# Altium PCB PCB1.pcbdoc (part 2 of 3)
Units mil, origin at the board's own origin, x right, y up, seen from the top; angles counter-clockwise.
Board outline 4706 x 2788 mil, 2 copper layers (Top Layer, Bottom Layer); 153 components, 206 nets, 1095 pads, 513 vias.
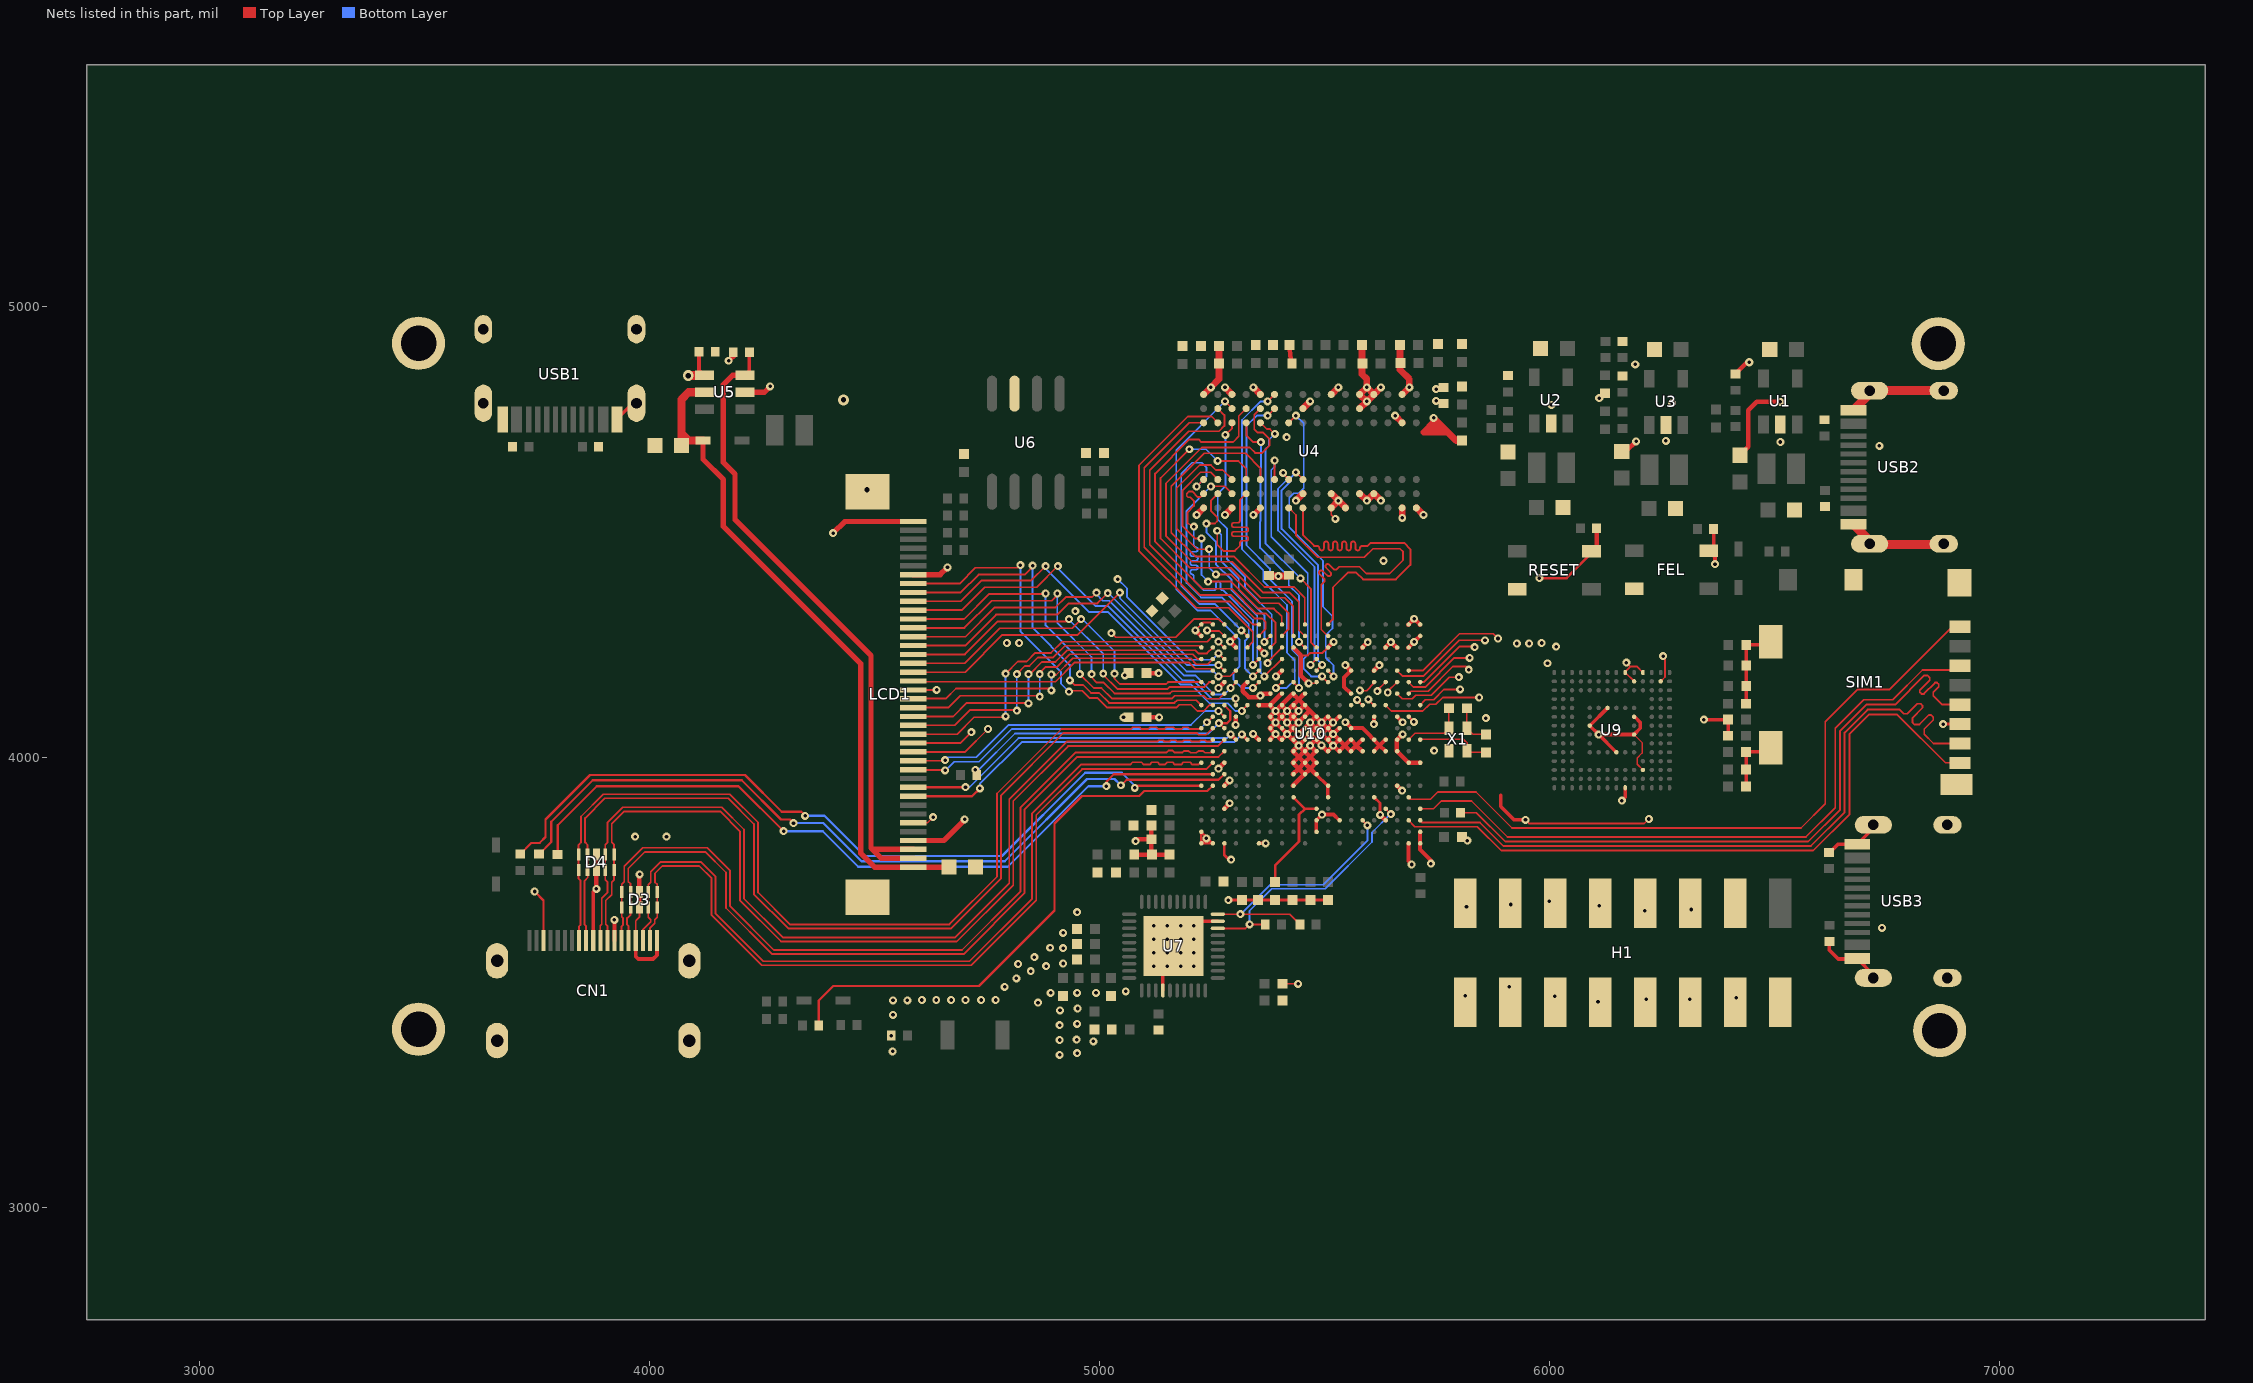
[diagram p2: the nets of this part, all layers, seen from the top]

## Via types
v1: diameter 17.7, hole 7.9, Top Layer to Bottom Layer, 233 vias
v2: diameter 17.72, hole 7.87, Top Layer to Bottom Layer, 140 vias
v3: diameter 17.7, hole 8, Top Layer to Bottom Layer, 88 vias
v4: diameter 18, hole 8, Top Layer to Bottom Layer, 38 vias
v5: diameter 24, hole 15, Top Layer to Bottom Layer, 8 vias
v6: diameter 24, hole 12, Top Layer to Bottom Layer, 6 vias

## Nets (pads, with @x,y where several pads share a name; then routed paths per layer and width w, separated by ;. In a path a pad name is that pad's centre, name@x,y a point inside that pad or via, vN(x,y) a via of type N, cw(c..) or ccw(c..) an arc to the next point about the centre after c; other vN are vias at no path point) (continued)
FEL: FEL.2 R36.2 U10.A18 | length 2083.2
  Top Layer w6: U10.A18@5276.7,3808.37 5276.7,3782.8 5277.5,3782 ; v1(5292,3772.5) v1@5287,3772.5 ; 5277.5,3782 5286,3772.5 v1@5287,3772.5 ; 5277.5,3782 v1@5287,3772.5
  Top Layer w8: R36.2@6364,4506.5 6364,4470.1 FEL.2@6352.7,4458.8 6367,4444.5 v1(6367,4428.5)
  Mid-Layer 1 w6: v1(5292,3772.5) 5301,3781.5 5633,3781.5 5678,3736.5 5869,3736.5 5909,3776.5 5909,3920.5 5963,3974.5 5963,4047.5 5902,4108.5 5805,4108.5 5768,4145.5 5768,4204.5 5917,4353.5 6292,4353.5 v1(6367,4428.5)
GND: C1.1 C2.1 C3.1 C5.1 C6.1 C7.1 C8.1 C9.1 C11.1 C12.1 C13.1 C15.1 C16.1 C17.1 C18.1 C19.1 C20.1 C21.1 C22.1 C23.1 C24.1 C25.1 C26.1 C27.1 C28.1 C29.1 C30.1 C31.1 C32.2 C33.1 C34.1 C35.1 C36.2 C38.1 C39.1 C40.1 C41.1 C42.1 C43.1 C44.1 C45.1 C46.1 C47.1 C48.1 C49.1 C50.1 C51.1 C52.1 C53.1 C54.1 C55.2 C56.1 C57.1 C58.1 C59.2 C60.2 C61.2 C62.2 C63.2 C64.2 C65.2 C66.2 C67.2 C68.1 C69.2 C70.1 C71.2 C72.1 C73.2 C74.1 CN1.1 CN1.4 CN1.7 CN1.10 CN1.17 CN1.20 CN1.21 CN1.22 CN1.23 D3.3 D3.8 D4.3 D4.8 FEL.3 H1.14 H1.15 LCD1.4 LCD1.34 LCD1.40 LCD1.41 LCD1.42 pad.1 R2.1 R4.1 R6.1 R8.1 R9.2 R10.2 R12.1 R14.1 R15.1 R16.1 R17.1 R18.2 R19.2 R20.2 R21.1 R22.1 R29.1 R32.2 R33.2 RESET.3 SIM1.6 SIM1.9 SIM1.10 SIM1.11 SIM1.13 SIM1.14 U1.2 U2.2 U3.2 U4.A9 U4.B1 U4.B3 U4.B9 U4.D1 U4.D8 U4.E1 U4.E2 U4.E8 U4.F9 U4.G1 U4.G8 U4.G9 U4.J2 U4.J8 U4.M1 U4.M9 U4.P1 U4.P9 U4.T1 U4.T9 U5.2 U6.3 U7.4 U7.19 U7.41 U9.A6 U9.C4 U9.E7 U9.G5 U9.H10 U9.J5 U9.K8 U9.N2 U9.N5 U9.P4 U9.P6 U10.A1 U10.A2 U10.A15 U10.A19 U10.A20 U10.B1 U10.B10 U10.B20 U10.C4 U10.C8 U10.C10 U10.D18 U10.E5 U10.E9 U10.F3 U10.F9 U10.F12 U10.F18 U10.G10 U10.G11 U10.G12 U10.H1 U10.H2 U10.H10 U10.H11 U10.H12 U10.H18 U10.J3 U10.J6 U10.J7 U10.J8 U10.J9 U10.J10 U10.J11 U10.J12 U10.K3 U10.K6 U10.K7 U10.K8 U10.K9 U10.K10 U10.K11 U10.K12 U10.K13 U10.K14 U10.L8 U10.L9 U10.L10 U10.L11 U10.L12 U10.L13 U10.L14 U10.L18 U10.M3 U10.M5 U10.M8 U10.M9 U10.M10 U10.M11 U10.M12 U10.M13 U10.M14 U10.N11 U10.N12 U10.N13 U10.N14 U10.N15 U10.N18 U10.P7 U10.P11 U10.P12 U10.P13 U10.R10 U10.R18 U10.T5 U10.T7 U10.T13 U10.V2 U10.V3 U10.V4 U10.V6 U10.V9 U10.V12 U10.V15 U10.V17 U10.W1 U10.W17 U10.W20 U10.Y1 U10.Y2 U10.Y19 U10.Y20 USB1.13 USB1.14 USB1.15 USB1.16 USB1.A1B12 USB1.B1A12 USB2.13 USB2.14 USB2.15 USB2.16 USB2.A1B12 USB2.B1A12 USB3.13 USB3.14 USB3.15 USB3.16 USB3.A1B12 USB3.B1A12 X1.2 X1.4 | length 9502.7
  Top Layer w3.5: C36.2@5816,4108.5 X1.2@5816,4064.5 5830,4050.5 C32.2@5858,4050.51 ; U9.G5@6187.24,4050.18 6205.02,4032.39 6205.02,4009.03 6194.02,3998.03 6194.02,3984.34 U9.C4@6206.92,3971.44 ; U9.N2@6246.29,4168.29 6256,4178 6256,4214.5 6256,4220.5 v1(6252,4224.5)
  Top Layer w4: CN1.4@3969.5,3592.7 3969.5,3636 3971,3637.5 3977.7,3644.2 D3.8@3977.7,3665.5 ; v2(5212.54,4281.78) 5212.71,4281.78 5229.93,4299 5246.7,4299 U10.Y19@5251.11,4294.59 ; v3(5265,4075.5) 5265,4075.99 5265.48,4075.5 U10.L18@5276.7,4064.28 ; U10.R18@5276.7,4166.2 U10.R18@5276.7,4166.64 ; C60.2@5406,3496.5 v1(5441,3496.5) ; v2(5464.24,4163.89) 5478.68,4163.89 U10.R10@5481.43,4166.64 ; U4.G9@5514.5,4553.65 5514.5,4538.15 v2(5523.5,4529.15) ; v2(5530.49,4569.65) U4.F9@5546,4553.65 ; v1(5946,3860.5) 5954,3852.5 5982.5,3852.5 6210,3852.5 v1(6220,3862.5) ; v1(6170.02,4210.02) 6179.02,4201.02 ; U9.N5@6187.24,4168.29 U9.P6@6167.55,4187.98 6167.55,4189.55 6179.02,4201.02 ; U9.P4@6206.92,4187.98 6193.87,4201.02 6179.02,4201.02
  Top Layer w4.5: 5447.24,4226.2 5462.54,4226.2 5467.58,4231.24 5494.68,4231.24 U10.V9@5506.83,4243.39
  Top Layer w5: v1(3745,3701.5) 3764.8,3681.7 CN1.17@3764.8,3591.7 ; v3(5265,4075.5) 5265.48,4075.5 5283,4075.5 5290,4082.5 5290,4102.17 U10.N18@5276.7,4115.46 ; v1(5288.88,3948.5) v1@5289,3948.5
  Top Layer w6: v1(5286,3682.51) C2.1@5316,3682.51 C3.1@5352,3682.51 C9.1@5390,3682.51 C23.1@5428,3682.51 C19.1@5468,3682.51 C21.1@5507,3682.51 ; U10.E5@5609.88,3910.88 5623,3897.76 v1(5623,3871.5) ; v1(6874,4073.5) SIM1.6@6911.1,4073.5 ; U10.A20@5225.87,3808.37 v1(5237,3819.5) ; U10.A20@5225.87,3808.37 5225.52,3808.37 5225.52,3833.96 5237,3822.49 v1(5237,3819.5) ; U10.A20@5225.87,3808.37 5251.11,3808.37 5239.98,3819.5 v1(5237,3819.5)
  Top Layer w8: CN1.10@3875,3592.7 3875,3700.5 v3(3882,3707.5) ; CN1.7@3922.2,3592.7 v1@3922.2,3638.5 ; USB1.A1B12@3928.28,4751.52 3964.3,4787.54 USB1.13@3971.38,4787.54 ; CN1.4@3969.5,3592.7 3969.5,3557 3975,3551.5 4008,3551.5 4016.7,3560.2 CN1.1@4016.7,3592.7 ; U7.4@5140.54,3481.8 5140.54,3526.04 v4(5150,3535.5) ; v4(5209,3625.5) 5218.81,3635.32 U7.19@5262.56,3635.32 ; U10.A15@5353.47,3808.37 v1(5368.87,3808.37) v1@5369,3808.5 ; U10.G10@5480.43,3961.71 5507.02,3936.32 U10.E9@5507.02,3910.73 ; U10.B10@5481.43,3833.96 5481.43,3859.55 v1(5494,3872.12) 5494,3872.5 5519.66,3872.5 U10.C8@5532.61,3859.55 ; U10.M5@5609.38,4089.87 v1@5609.38,4075.88 ; U10.M3@5660.63,4089.87 v1(5673,4077.5) ; U10.A2@5686.15,3808.37 5686.15,3768.35 v1(5693,3761.5) ; U10.B1@5711.74,3833.96 5711.74,3794.76 5736,3770.5 v1(5736,3763.5) ; 5891,3915.5 5891,3890.5 5921,3860.5 v1(5946,3860.5) ; U9.K8@6128.18,4109.24 U9.H10@6088.81,4069.87 v1(6108.5,4050.18) ; U9.E7@6147.87,4010.81 v1(6108.5,4050.18) ; v1(6160,3903.5) 6167.55,3911.05 U9.A6@6167.55,3932.07 ; U9.J5@6187.24,4089.55 6188.5,4089.55 6201.02,4077.03 6201.02,4063.97 U9.G5@6187.24,4050.18 v1(6108.5,4050.18) ; v1@6342,4083.5 v1(6342.3,4083.2) C28.1@6395.95,4083.2 ; C29.1@6396,4047.5 C28.1@6395.95,4083.2 ; C68.1@6435.99,3934.5 C70.1@6435.99,3972.5 C72.1@6435.99,4011.5 6481.5,4011.5 SIM1.14@6490.9,4020.9 ; C25.1@6435.99,4118.5 6436.36,4118.87 C73.2@6436.36,4157.85 C71.2@6436.36,4203.53 C69.2@6436.36,4249.22 6484.12,4249.22 SIM1.13@6490.9,4256 ; R20.2@6620,3788.5 6622.4,3788.5 6640.17,3806.27 USB3.B1A12@6682.71,3806.27 6718.73,3842.29 USB3.14@6718.73,3849.58 ; R17.1@6621,3590.5 6621,3571.5 6641,3551.5 6681.68,3551.5 USB3.A1B12@6682.71,3552.53 6718.73,3516.51 USB3.13@6718.73,3509.43 ; v1@5609.38,4075.88 5609,4075.5 5609.38,4073.5 v1@5609.38,4075.88
  Top Layer w9: U10.T7@5558.01,4192.21 5543,4177.2 5543,4156.26 U10.P7@5558.2,4141.05 ; U10.K7@5558.2,4038.68 5570.6,4026.29 5583.39,4013.49 U10.J6@5583.79,4013.09
  Top Layer w10: v3(3882,3707.5) D4.8@3882,3749.2 D4.3@3882,3783.8 ; D3.8@3977.7,3665.5 D3.3@3977.7,3700.1 3977.7,3739.2 v3(3978,3739.5) ; C59.2@5077,3783.51 C66.2@5116,3783.51 ; v1(5080,3813.5) 5084,3817.5 C30.1@5115,3817.5 ; C1.1@5115,3848.5 C30.1@5115,3817.5 ; C64.2@5155,3783.51 C66.2@5116,3783.51 ; v2(5212.54,4281.78) U10.W20@5225.33,4268.98 ; v1(5264,3974.5) 5277,3987.5 U10.H18@5276.7,3987.5 ; v1(5264,4153.5) 5264,4153.94 U10.R18@5276.7,4166.64 ; U10.D18@5276.7,3885.14 v1@5289,3897.44 ; U10.F18@5276.7,3936.32 v1(5288.88,3948.5) ; U10.V17@5302.1,4243.39 5302.1,4244.39 v2(5290,4256.5) 5302.1,4268.61 U10.W17@5302.1,4268.98 ; U10.N15@5352.47,4115.26 U10.N14@5378.06,4115.26 ; U10.V15@5353.28,4243.39 v2(5366.08,4230.6) ; U10.K14@5378.06,4038.48 v1(5390.86,4051.28) ; v2(5391.67,4179.42) U10.T13@5404.46,4192.21 ; U10.P13@5402.21,4139.42 U10.N14@5378.06,4115.26 ; C39.1@5421.71,4915.46 ccw(c5571.82,4915.46) R14.1@5427.5,4874.16 ; U10.F12@5429.24,3936.12 U10.G11@5454.83,3961.71 ; U10.G12@5429.24,3961.71 5442.04,3974.51 ; U10.V12@5430.05,4243.39 5447.24,4226.2 5447.24,4180.89 v2(5464.24,4163.89) ; v1(5442.04,4102.47) U10.M12@5429.24,4089.67 ; U10.P11@5453.39,4139.42 5442.04,4128.06 ; 5467.02,4101.86 5467.02,4103.08 ; U10.J10@5480.42,4012.89 5467.63,4000.1 ; U10.G10@5480.43,3961.71 5467.63,3974.51 ; U10.J10@5480.43,4012.89 v1(5467.63,4025.69) ; U10.V9@5506.83,4243.39 v2(5519.63,4256.19) ; U10.L8@5531.61,4064.07 v1(5518.82,4051.28) ; U10.M8@5531.61,4089.67 v1(5518.82,4076.88) ; v2(5546.01,4204.21) U10.T7@5558.01,4192.21 ; U10.K7@5557.2,4038.48 5544.41,4025.69 ; U10.K6@5582.79,4038.48 5570.6,4026.29 5570,4025.69 ; U10.J6@5583.39,4013.49 5570,4025.69 ; U10.V6@5583.6,4243.39 v2(5595.6,4255.39) ; U10.T5@5609.19,4192.21 v2(5621.19,4204.21) ; v1(5623,3871.5) 5623.67,3871.5 U10.C4@5635.47,3859.7 ; U10.V4@5634.78,4243.39 v2(5646.78,4255.39) U10.V3@5660.37,4243.39 ; U10.F3@5660.56,3936.32 5671.39,3925.5 v1(5672,3925.5) ; v1(5673,4050.5) 5672.38,4050.5 5660.56,4038.68 5660.56,4013.09 5686.15,3987.5 U10.H1@5711.74,3987.5 ; U10.V2@5685.96,4243.39 v2(5698.76,4256.19) U10.W1@5711.55,4268.98 ; U10.Y2@5685.96,4294.57 v2(5698.76,4307.37) U10.Y1@5711.55,4294.57 ; C16.1@6159.87,4678.92 6169.4,4678.92 v4(6191.87,4701.4) ; R2.1@6412.14,4851.11 6438.15,4877.11 v4(6443.14,4877.11) ; C6.1@6422.14,4670.64 6441,4689.49 6441,4739.5 6441,4770.5 6460,4789.5 6511.75,4789.5 v4(6512.14,4789.11) ; USB2.A1B12@6674.55,4509.87 USB2.A1B12@6674.55,4516.95 ; C30.1@5115,3817.5 5115,3784.5 C66.2@5116,3783.51 ; U10.N14@5378.06,4115.26 v1(5390.86,4102.47) ; v1(5390.86,4051.28) 5378.06,4064.08 v1(5390.86,4076.88) ; v1(5390.86,4051.28) 5403.65,4038.49 v1(5416.45,4051.28) ; v1(5390.86,4076.88) U10.M13@5403.65,4089.67 ; v1(5390.86,4076.88) 5378.06,4089.67 v1(5390.86,4102.47) ; v1(5390.86,4076.88) v1(5416.45,4051.28) ; v1(5390.86,4102.47) U10.N13@5403.65,4115.26 ; v1(5390.86,4102.47) U10.M13@5403.65,4089.67 ; U10.M13@5403.65,4089.67 v1(5416.45,4102.47) ; U10.M13@5403.65,4089.67 v1@5416.45,4076.87 ; U10.N13@5403.65,4115.26 v1(5416.45,4102.47) ; U10.N13@5403.65,4115.26 5429.24,4140.85 5442.04,4128.06 ; v1(5416.45,4051.28) U10.L12@5429.25,4064.08 ; v1(5416.45,4051.28) U10.K12@5429.25,4038.49 ; v1@5416.47,4076.86 U10.M12@5429.24,4089.67 ; v1@5416.47,4076.86 U10.L12@5429.25,4064.08 ; v1(5416.45,4102.47) U10.M12@5429.24,4089.67 ; v1(5416.45,4102.47) U10.N12@5429.24,4115.26 ; U10.K12@5429.25,4038.49 v1(5442.04,4051.28) ; U10.K12@5429.25,4038.49 v1(5442.04,4025.69) ; U10.L12@5429.25,4064.08 v1(5442.04,4051.28) ; U10.L12@5429.25,4064.08 v1(5442.04,4076.87) ; U10.M12@5429.24,4089.67 v1(5442.04,4076.87) ; U10.N12@5429.24,4115.26 5442.04,4128.06 ; U10.N12@5429.24,4115.26 v1(5442.04,4102.47) U10.N11@5454.84,4115.27 ; 5442.04,3974.51 5429.24,3987.3 5442.04,4000.1 ; 5442.04,3974.51 U10.G11@5454.83,3961.71 ; 5442.04,3974.51 U10.H11@5454.84,3987.31 ; 5442.04,4000.1 5429.25,4012.89 v1(5442.04,4025.69) ; 5442.04,4000.1 U10.H11@5454.84,3987.31 ; 5442.04,4000.1 U10.J11@5454.83,4012.89 ; v1(5442.04,4025.69) U10.J11@5454.83,4012.89 ; v1(5442.04,4025.69) U10.J11@5454.84,4012.9 ; v1(5442.04,4025.69) v1(5467.63,4051.28) ; v1(5442.04,4051.28) v1(5467.63,4076.87) ; v1(5442.04,4076.87) 5442.04,4078.1 5467.02,4103.08 ; 5442.04,4128.06 U10.N11@5454.84,4115.27 ; U10.G11@5454.83,3961.71 5467.63,3974.51 ; U10.H11@5454.84,3987.31 5467.63,3974.51 ; U10.H11@5454.84,3987.31 5467.63,4000.1 ; U10.J11@5454.84,4012.9 v1(5467.63,4025.69) ; U10.J11@5454.84,4012.9 5467.63,4000.1 ; U10.N11@5454.84,4115.27 5467.02,4103.08 ; 5467.02,4103.08 U10.M10@5480.43,4089.67 ; 5467.63,3974.51 5480.42,3987.3 5467.63,4000.1 ; v1(5467.63,4025.69) U10.K10@5480.43,4038.49 ; v1(5467.63,4051.28) U10.K10@5480.43,4038.49 ; v1(5467.63,4051.28) U10.L10@5480.43,4064.08 ; v1(5467.63,4076.87) U10.L10@5480.43,4064.08 ; v1(5467.63,4076.87) U10.M10@5480.43,4089.67 ; U10.K10@5480.43,4038.49 v1(5493.22,4051.28) ; U10.K10@5480.43,4038.49 v1(5492.91,4026.01) 5506.02,4012.89 v1(5518.82,4025.69) ; U10.L10@5480.43,4064.08 v1(5493.22,4051.28) ; U10.L10@5480.43,4064.08 v1(5493.23,4076.88) ; U10.M10@5480.43,4089.67 v1(5493.23,4076.88) ; v1(5493.22,4051.28) U10.L9@5506.02,4064.08 ; v1(5493.22,4051.28) U10.K9@5506.02,4038.48 ; v1(5493.23,4076.88) 5506.02,4089.67 v1(5518.82,4076.88) ; v1(5493.23,4076.88) U10.L9@5506.02,4064.08 ; U10.K9@5506.02,4038.48 v1(5518.82,4025.69) ; U10.K9@5506.02,4038.48 v1(5518.82,4051.28) ; U10.L9@5506.02,4064.08 v1(5518.82,4076.88) ; U10.L9@5506.02,4064.08 v1(5518.82,4051.28) ; v1(5518.82,4025.69) U10.K8@5531.62,4038.49 ; v1(5518.82,4025.69) 5531.61,4012.89 5544.41,4025.69 ; v1(5518.82,4051.28) U10.K8@5531.62,4038.49 ; U10.K8@5531.62,4038.49 5544.41,4025.69 ; 5544.41,4025.69 5557.2,4012.9 5570,4025.69
  Top Layer w12: v1(4176,4880.5) 4186,4890.5 R22.1@4186,4899.5 ; U5.2@4212.24,4810.5 4255,4810.5 v1(4268,4823.5) ; v1(4408,4497.5) 4433.9,4523.4 LCD1.40@4585.7,4523.4 ; LCD1.4@4585.7,3814.7 4654.2,3814.7 4700,3860.5 v1(4700,3861.5) ; LCD1.34@4585.7,4405.3 4645.8,4405.3 v1(4662,4421.5) ; v2(5341.52,4538.16) U4.M9@5357,4553.64
  Top Layer w15: v2(5215.54,4538.16) U4.T9@5231.28,4553.9 ; U4.T1@5231.28,4805.86 v2(5247.03,4821.61) 5265,4839.58 5265,4876.5 C43.1@5265,4914.5 ; v2(5278.53,4538.16) U4.P9@5294.27,4553.9 ; v2(5278.53,4821.61) U4.P1@5294.27,4805.86 ; v2(5341.52,4821.61) U4.M1@5357.26,4805.86 ; R10.2@5376.24,4402.16 v2(5397.24,4402.16) R9.2@5418.24,4402.16 ; v2(5436.01,4569.65) U4.J8@5451.75,4585.39 ; U4.J2@5451.75,4774.37 v2(5467.5,4790.12) ; U4.G9@5514.5,4553.65 v2(5530.49,4569.65) ; U4.G8@5514.5,4585.15 5514.98,4585.15 v2(5530.49,4569.65) ; U4.G1@5514.74,4805.86 v2(5530.49,4821.61) ; U4.F9@5546,4553.65 5546,4554.14 v2(5530.49,4569.65) ; U4.E8@5577.74,4585.39 v2(5593.49,4569.65) 5609.23,4585.39 v2(5624.98,4569.65) ; U4.E2@5577.74,4774.37 v2(5593.49,4790.12) ; C46.1@5583,4915.5 5583,4850.49 5593.49,4840.01 v2(5593.49,4821.61) ; v2(5624.98,4821.61) U4.D1@5609.23,4805.86 ; v2(5656.48,4758.62) U4.B3@5672.22,4742.87 ; C45.1@5667,4915.5 5667,4860.49 5687.97,4839.53 v2(5687.97,4821.61) U4.B1@5672.22,4805.86 ; v2(5672.22,4531.63) U4.B9@5672.22,4553.9 ; U4.A9@5703.72,4553.9 v2(5719.47,4538.16) ; 5742,4731.5 5764,4731.5 ; C51.1@5805,4703.51 5791.99,4703.51 5774,4721.5 ; v2(5593.49,4790.12) 5577.74,4805.86 v2(5593.49,4821.61) ; v2(5593.49,4790.12) U4.D1@5609.23,4805.86 ; v2(5593.49,4821.61) U4.D1@5609.23,4805.86 ; 5764,4731.5 5774,4721.5 ; 5764,4731.5 v1(5742,4753.5) 5742,4743.5 5720,4721.5 5774,4721.5
  Top Layer w20: USB2.A1B12@6674.55,4516.95 USB2.13@6717.65,4473.85 ; USB2.B1A12@6674.55,4770.69 6710.57,4806.71 USB2.14@6710.57,4814 USB2.16@6875.14,4814 ; USB2.13@6710.57,4471.85 USB2.15@6875.14,4471.85
  Mid-Layer 1 w10: v1(5623,3871.5) 5622,3872.5 5622,3900.5 5647,3925.5 v1(5672,3925.5)
  Mid-Layer 2 w8: v2(5467.5,4790.12) 5498.99,4821.61 v2(5530.49,4821.61)
  Mid-Layer 2 w12: v2(5212.54,4281.78) 5212.54,4289.04 5232,4308.5 5257,4308.5 5290,4275.5 v2(5290,4256.5)
  Bottom Layer w4: v1(4724,3971.5) 4731,3971.5 4812,4052.5 4901,4052.5 5242,4052.5 v3(5265,4075.5)
  other v1: 4537,3381.5 6738,3620.5 3922,3638.5 5289,3897.5 5609,4073.5 5416.45,4076.88 5053,4088.5 5056,4181.5 4794,4253.5 4821,4253.5 4946,4324.5
  other v2: 5415.37,4711.03
  other v3: 4911,3338.5 4950,3342.5 4540,3346.5 4986,3368.5 4911,3371.5 4949,3372.5 4911,3404.5 4950,3407.5 4541,3427.47 4912,3437.5 4951,3441.5 4863,3454.5 4541,3459.53 4573.03,3459.5 4604.97,3460.5 4637.03,3460.5 4669.97,3460.5 4702.03,3460.5 4736.94,3460.5 4769,3460.5 4891,3476.5 4950,3476.5 4992,3476.5 5058,3479.5 4789,3489.5 4815,3508.5 4847,3524.5 4881,3535.5 4819,3540.5 4919,3541.5 4855,3555.5 4890,3576.5 4919,3575.5 4919,3609.5 4950,3655.5 5817,3814.5 3968,3823.5 4037.71,3823.5 5743,4014.5 5858,4086.5
  other v4: 5120,3535.5 5180,3535.5 5209,3535.5 5120,3565.5 5150,3565.5 5180,3565.5 5209,3565.5 5120,3595.5 5150,3595.5 5180,3595.5 5209,3595.5 5120,3625.5 5150,3625.5 5180,3625.5 5630.5,4436.15 6732,4691.5 6512.14,4700.11 6257.87,4702.4 6003.87,4782.4 6271.87,4786.4 6109.87,4797.4 6189.87,4872.4
  other v6: 4483.31,4593.9 4431,4793.5
H_D0+: CN1.8 D4.1 D4.10 U10.K18 | length 2147.2
  Top Layer w4: CN1.8@3906.5,3592.7 3906.5,3625 3903,3628.5 3903,3681.5 3916.05,3694.55 3916.05,3722.45 3921.4,3727.8 D4.10@3921.4,3749.2 D4.1@3921.4,3783.8 3921.4,3805.2 3916.05,3810.55 3916.05,3851.55 3944,3879.5 4157,3879.5 4201,3835.5 4201,3681.77 4292.27,3590.5 4682.73,3590.5 4808,3715.77 4808,3902.5 4930,4024.5 5262.52,4024.5 U10.K18@5276.7,4038.68
H_D0-: CN1.9 D4.2 D4.9 U10.K19 | length 2142.6
  Top Layer w4: CN1.9@3890.8,3592.7 3890.8,3625.3 3894,3628.5 3894,3686.5 3907.05,3699.55 3907.05,3722.45 3901.7,3727.8 D4.9@3901.7,3749.2 D4.2@3901.7,3783.8 3901.7,3805.2 3907.05,3810.55 3907.05,3855.28 3940.27,3888.5 4160.73,3888.5 4210,3839.23 4210,3685.5 4296,3599.5 4679,3599.5 4799,3719.5 4799,3906.23 4927.27,4034.5 5128,4034.5 5131,4037.5 5141,4037.5 5144,4034.5 5155,4034.5 5158,4037.5 5169,4037.5 5172,4034.5 5184,4034.5 5187,4037.5 5201,4037.5 5204,4034.5 5221,4034.5 5224,4037.5 5235,4037.5 5238,4034.5 5246.93,4034.5 U10.K19@5251.11,4038.68
H_D1+: CN1.5 D3.4 D3.7 U10.J18 | length 1941.4
  Top Layer w4: CN1.5@3953.7,3592.7 3953.7,3624.27 3950.35,3627.62 3950.35,3642.5 3958,3650.15 D3.7@3958,3665.5 D3.4@3958,3700.1 3958,3718.5 3953,3723.5 3953,3752.5 3990,3789.5 4124.27,3789.5 4170,3743.77 4170,3664.77 4272.27,3562.5 4698,3562.5 4833,3697.5 4833,3883.5 4950,4000.5 5264.11,4000.5 U10.J18@5276.7,4013.09
H_D1-: CN1.6 D3.5 D3.6 U10.J19 | length 1936
  Top Layer w4: CN1.6@3938,3592.7 3938,3624.27 3941.35,3627.62 3941.35,3642.5 3938.3,3645.55 D3.6@3938.3,3665.5 D3.5@3938.3,3700.1 3938.3,3717.8 3944,3723.5 3944,3757.5 3985,3798.5 4128,3798.5 4179,3747.5 4179,3668.5 4276,3571.5 4694.27,3571.5 4824,3701.23 4824,3887.23 4947.27,4010.5 5149,4010.5 5153,4014.5 5162,4014.5 5166,4010.5 5184,4010.5 5187,4013.5 5198,4013.5 5202,4009.5 5215,4009.5 5219,4013.5 5230,4013.5 5234,4009.5 5247.52,4009.5 U10.J19@5251.11,4013.09
H_D2+: CN1.2 D3.1 D3.10 U10.H19 | length 1840.5
  Top Layer w4: CN1.2@4001,3592.7 4001,3619.77 4011.75,3630.52 4011.75,3638.75 4017.1,3644.1 D3.10@4017.1,3665.5 D3.1@4017.1,3700.1 4017.1,3717.4 4012,3722.5 4012,3741.5 4028.64,3758.14 4110.64,3758.14 4138,3730.77 4138,3648.77 4249.27,3537.5 4714.73,3537.5 4859,3681.77 4859,3871.5 4961,3973.5 5237.11,3973.5 U10.H19@5251.11,3987.5
H_D2-: CN1.3 D3.2 D3.9 U10.H20 | length 1846.6
  Top Layer w4: CN1.3@3985.2,3592.7 3985.2,3616.7 4002.75,3634.25 4002.75,3638.75 3997.4,3644.1 D3.9@3997.4,3665.5 D3.2@3997.4,3700.1 3997.4,3716.9 4003,3722.5 4003,3745.23 4024.91,3767.14 4114.36,3767.14 4147,3734.5 4147,3652.5 4253,3546.5 4711,3546.5 4850,3685.5 4850,3875.23 4958.27,3983.5 5068,3983.5 5073,3988.5 5093,3988.5 5098,3983.5 5111,3983.5 5116,3988.5 5129,3988.5 5134,3983.5 5145,3983.5 5150,3988.5 5162,3988.5 5167,3983.5 5181,3983.5 5186,3988.5 5201,3988.5 5206,3983.5 5219.52,3983.5 5224.52,3988.5 U10.H20@5225.52,3987.5
H_DC+: CN1.11 D4.4 D4.7 U10.L19 | length 2197.9
  Top Layer w4: CN1.11@3859.3,3592.7 3859.3,3624.27 3855.9,3627.67 3855.9,3725.4 3863,3732.5 3863,3748.5 D4.7@3862.3,3749.2 D4.4@3862.3,3783.8 3862.3,3805.2 3856.95,3810.55 3856.95,3864.45 3901,3908.5 4175,3908.5 4232,3851.5 4232,3695.77 4308.27,3619.5 4670,3619.5 4781,3730.5 4781,3915.5 4919,4053.5 5216,4053.5 5220,4049.5 5236.33,4049.5 U10.L19@5251.11,4064.28
H_DC-: CN1.12 D4.5 D4.6 U10.L20 | length 2191.9
  Top Layer w4: CN1.12@3843.5,3592.7 3843.5,3624.27 3846.9,3627.67 3846.9,3725.6 3842.6,3729.9 D4.6@3842.6,3749.2 D4.5@3842.6,3783.8 3842.6,3805.2 3847.95,3810.55 3847.95,3868.18 3897.27,3917.5 4178.73,3917.5 4241,3855.23 4241,3699.5 4312,3628.5 4666.27,3628.5 4772,3734.23 4772,3919.23 4915.27,4062.5 5070,4062.5 5074,4066.5 5089,4066.5 5093,4062.5 5108,4062.5 5112,4066.5 5126,4066.5 5130,4062.5 5144,4062.5 5148,4066.5 5164,4066.5 5168,4062.5 5182,4062.5 5186,4066.5 5196,4066.5 5200,4062.5 5223.74,4062.5 U10.L20@5225.52,4064.28
H_DCEC: R39.2 U10.F19 | length 1241.7
  Top Layer w5: R39.2@4376,3403.5 4376,3459.5 4408,3491.5 4732,3491.5 4900,3659.5 4900,3852.5 4961,3913.5 5088,3913.5 5099,3924.5 5239.29,3924.5 U10.F19@5251.11,3936.32
H_DET: R44.2 U10.F20 | length 1778.5
  Top Layer w5: R44.2@3713,3784.5 3737.99,3809.5 3756,3809.5 3769,3822.5 3769,3861.5 3868,3960.5 4212,3960.5 4294,3878.5 4337,3878.5 v1(4346,3869.5) ; v1(5078,3931.5) 5082.82,3936.32 U10.F20@5225.52,3936.32
  Bottom Layer w5: v1(4346,3869.5) 4389,3869.5 4478,3780.5 4783,3780.5 4968,3965.5 5049,3965.5 5078,3936.5 v1(5078,3931.5)
H_SCL: R40.2 U10.G19 | length 1721.2
  Top Layer w5: R40.2@3796,3783.5 3796,3848.5 3883,3935.5 4198,3935.5 v1(4298,3835.5) ; v1(5015,3935.5) 5015,3945.5 5031.41,3961.91 U10.G19@5251.11,3961.91
  Bottom Layer w5: v1(4298,3835.5) 4385,3835.5 4464,3756.5 4796,3756.5 4975,3935.5 v1(5015,3935.5)
H_SDA: R41.2 U10.G18 | length 1782.3
  Top Layer w5: R41.2@3755,3784.5 3782,3811.51 3782,3856.5 3874,3948.5 4205,3948.5 4292,3861.5 4312,3861.5 v1(4320,3853.5) ; v1(5047,3937.5) 5048,3937.5 5060,3949.5 5264.29,3949.5 U10.G18@5276.7,3961.91
  Bottom Layer w5: v1(4320,3853.5) 4386,3853.5 4471,3768.5 4789,3768.5 4972,3951.5 5033,3951.5 v1(5047,3937.5)
HPVCC: C9.2 U10.D10 U10.E12 | length 251.7
  Top Layer w6: C9.2@5390,3722.51 5390,3759.5 5443,3812.5 5443,3872.31 5455.83,3885.14 ; U10.E12@5430.24,3910.73 5455.83,3885.14 ; U10.D10@5481.43,3885.14 5455.83,3885.14
HXIN: C32.1 U10.K1 X1.1 | length 167.3
  Top Layer w3.5: U10.K1@5711.74,4038.68 5712.56,4039.5 5808,4039.5 5816.56,4030.94 X1.1@5816.56,4015.97 ; X1.1@5816,4014.5 5820,4010.5 C32.1@5858,4010.51
HXOUT: C36.1 U10.K2 X1.3 | length 144.5
  Top Layer w3.5: U10.K2@5686.15,4038.68 5700.97,4053.5 5765,4053.5 X1.3@5776,4064.5 C36.1@5776,4108.5
LCD_CLK: LCD1.12 U10.M19 | length 715.6
  Top Layer w4: LCD1.12@4585.7,3972.2 4586.4,3971.5 4656,3971.5 v1(4657,3970.5) ; v1(5238,4077.5) 5238.74,4077.5 U10.M19@5251.11,4089.87
  Bottom Layer w4: v1(4657,3970.5) 4658,3970.5 4677,3989.5 4732,3989.5 4805,4062.5 5223,4062.5 v1(5238,4077.5)
LCD_D2: LCD1.16 U10.W19 | length 811.4
  Top Layer w4: LCD1.16@4585.7,4050.9 4683.4,4050.9 4721,4088.5 4789,4088.5 v1(4791,4090.5) ; v1(4791,4185.5) 4818,4212.5 4838,4212.5 4857,4231.5 4892,4231.5 4917,4256.5 5238.61,4256.5 U10.W19@5251.11,4269
  Bottom Layer w4: v1(4791,4090.5) v1(4791,4185.5)
LCD_D3: LCD1.17 U10.V20 | length 768.2
  Top Layer w4: LCD1.17@4585.7,4070.6 4678.1,4070.6 4712.35,4104.85 4814.65,4104.85 v1(4816,4103.5) ; v1(4816,4184.5) 4834,4202.5 4844,4202.5 4863,4221.5 4897,4221.5 4923,4247.5 5221.44,4247.5 U10.V20@5222.22,4246.72 ; U10.V20@5222.22,4246.72 5225.09,4243.41 5225.52,4243.41 U10.V20@5222.22,4246.72
  Bottom Layer w4: v1(4816,4103.5) v1(4816,4184.5)
LCD_D4: LCD1.18 U10.V19 | length 773.5
  Top Layer w4: LCD1.18@4585.7,4090.3 4674.8,4090.3 4705,4120.5 4841,4120.5 v1(4842,4119.5) ; v1(4842,4184.5) 4845,4184.5 4872,4211.5 4902,4211.5 4928,4237.5 5212,4237.5 5219,4230.5 5238.2,4230.5 U10.V19@5251.11,4243.41
  Bottom Layer w4: v1(4842,4119.5) v1(4842,4184.5)
LCD_D5: LCD1.19 U10.U20 | length 726
  Top Layer w4: LCD1.19@4585.7,4110 4663.5,4110 4690,4136.5 4865,4136.5 v1(4867,4134.5) ; v1(4867,4184.5) 4867,4187.5 4880,4200.5 4906,4200.5 4934,4228.5 5207,4228.5 5217.68,4217.82 U10.U20@5225.52,4217.82
  Bottom Layer w4: v1(4867,4134.5) v1(4867,4184.5)
LCD_D6: LCD1.20 U10.U19 | length 737.3
  Top Layer w4: LCD1.20@4585.7,4129.7 4586.5,4130.5 4659,4130.5 4681,4152.5 4889,4152.5 v1(4893,4148.5) ; v1(4893,4183.5) 4894,4182.5 4903,4182.5 4940,4219.5 5202,4219.5 5215,4206.5 5239.79,4206.5 U10.U19@5251.11,4217.82
  Bottom Layer w4: v1(4893,4148.5) v1(4893,4183.5)
LCD_D7: LCD1.21 U10.U18 | length 949.3
  Top Layer w4: LCD1.21@4585.7,4149.3 v1(4637.8,4149.3) v1@4638,4149.5 ; v1(5264.02,4230.5) U10.U18@5276.7,4217.82
  Mid-Layer 1 w4: v1(4637.8,4149.3) 4637.8,4251.3 4782,4395.5 v1(5040,4395.5)
  Bottom Layer w4: v1(5040,4395.5) 5061,4374.5 5061,4355.5 5200,4216.5 5250.02,4216.5 v1(5264.02,4230.5)
LCD_D10: LCD1.22 U10.T19 | length 691.4
  Top Layer w4: LCD1.22@4585.7,4169 4587.2,4167.5 4902,4167.5 4945,4210.5 5198,4210.5 5212,4196.5 5246.85,4196.5 U10.T19@5251.11,4192.23
LCD_D11: LCD1.23 U10.T18 | length 843
  Top Layer w4: LCD1.23@4585.7,4188.7 4701.2,4188.7 4784,4271.5 4951,4271.5 v1(5045,4365.5) ; v1(5264,4204.5) 5264.44,4204.5 U10.T18@5276.7,4192.23
  Bottom Layer w4: v1(5045,4365.5) 5045,4353.5 5194,4204.5 v1(5264,4204.5)
LCD_D12: LCD1.24 U10.R20 | length 777.6
  Top Layer w4: LCD1.24@4585.7,4208.4 4699.9,4208.4 4778,4286.5 4939,4286.5 v1(4959,4306.5) ; v1(5033,4185.5) 5033,4174.5 5045,4162.5 5148,4162.5 5152.14,4166.64 U10.R20@5225.52,4166.64
  Bottom Layer w4: v1(4959,4306.5) 4962,4306.5 5033,4235.5 v1(5033,4185.5)
LCD_D13: LCD1.25 U10.R19 | length 796.5
  Top Layer w4: LCD1.25@4585.7,4228.1 4700.6,4228.1 4774,4301.5 4927,4301.5 v1(4932,4306.5) ; v1(5008,4185.5) 5008,4182.5 5039,4151.5 5151,4151.5 5155,4155.5 5232,4155.5 5243.14,4166.64 U10.R19@5251.11,4166.64
  Bottom Layer w4: v1(4932,4306.5) 4932,4305.5 5008,4229.5 v1(5008,4185.5)
LCD_D14: LCD1.26 U10.T17 | length 846.8
  Top Layer w4: LCD1.26@4585.7,4247.8 4701.3,4247.8 4770,4316.5 4906,4316.5 4931,4341.5 4995,4341.5 v1(5018,4364.5) ; v1(5264,4179.5) 5289.56,4179.5 U10.T17@5302.29,4192.23
  Bottom Layer w4: v1(5018,4364.5) 5019,4364.5 5193,4190.5 5253,4190.5 v1(5264,4179.5)
LCD_D15: LCD1.27 U10.R17 | length 865.8
  Top Layer w4: LCD1.27@4585.7,4267.5 4702,4267.5 4767,4332.5 4902,4332.5 4925,4355.5 4983,4355.5 v1(4993,4365.5) ; v1(5291,4153.5) 5302.29,4164.79 U10.R17@5302.29,4166.64
  Bottom Layer w4: v1(4993,4365.5) 4993,4361.5 5007,4347.5 5021,4347.5 5187,4181.5 5212,4181.5 5254.35,4139.15 5276.65,4139.15 v1(5291,4153.5)
LCD_D18: LCD1.28 U10.P19 | length 860.1
  Top Layer w4: LCD1.28@4585.7,4287.1 4699.6,4287.1 4760,4347.5 4894,4347.5 4906,4359.5 v1(4906,4363.5) ; v1(4982,4184.5) 4982,4177.5 4994,4165.5 5009,4165.5 5033,4141.5 5156,4141.5 5161,4146.5 5245.66,4146.5 U10.P19@5251.11,4141.05
  Bottom Layer w4: v1(4906,4363.5) 4906,4298.5 4982,4222.5 v1(4982,4184.5)
LCD_D19: LCD1.29 U10.P18 | length 881.5
  Top Layer w4: LCD1.29@4585.7,4306.8 4699.3,4306.8 4755,4362.5 4879,4362.5 v1(4880,4363.5) ; v1(4956,4184.5) 4987,4153.5 5004,4153.5 5027,4130.5 5161,4130.5 5167,4136.5 5231,4136.5 5238,4129.5 5265.15,4129.5 U10.P18@5276.7,4141.05
  Bottom Layer w4: v1(4880,4363.5) 4880,4292.5 4956,4216.5 v1(4956,4184.5)
LCD_D20: LCD1.30 U10.N17 | length 897.8
  Top Layer w4: LCD1.30@4585.7,4326.5 4694,4326.5 4745,4377.5 4860,4377.5 v1(4907,4424.5) ; v1@5302,4130.5 v1(5302.29,4130.21) U10.N17@5302.29,4115.46
  Bottom Layer w4: v1(4907,4424.5) 4907,4419.5 4991,4335.5 5019,4335.5 5184,4170.5 5208,4170.5 5249,4129.5 5301.58,4129.5 v1(5302.29,4130.21)
LCD_D21: LCD1.31 U10.N16 | length 917.7
  Top Layer w4: LCD1.31@4585.7,4346.2 4691.7,4346.2 4738,4392.5 4848,4392.5 v1(4880,4424.5) ; v1(5316,4102.5) 5316,4103.58 U10.N16@5328,4115.58
  Bottom Layer w4: v1(4880,4424.5) 4880,4418.5 4976,4322.5 5018,4322.5 5179,4161.5 5202,4161.5 5244,4119.5 5284.15,4119.5 5301.15,4102.5 v1(5316,4102.5)
LCD_D22: LCD1.32 U10.N20 | length 900.4
  Top Layer w4: LCD1.32@4585.7,4365.9 4691.4,4365.9 4731,4405.5 4834,4405.5 4851,4422.5 v1(4851,4425.5) ; v1(4934,4170.5) 4944,4160.5 4963,4160.5 4981,4142.5 4999,4142.5 5021,4120.5 5166,4120.5 5172,4126.5 5214.48,4126.5 U10.N20@5225.52,4115.46
  Bottom Layer w4: v1(4851,4425.5) 4851,4287.5 4934,4204.5 v1(4934,4170.5)
LCD_D23: LCD1.33 U10.N19 | length 929.9
  Top Layer w4: LCD1.33@4585.7,4385.6 4689.1,4385.6 4724,4420.5 4818,4420.5 v1(4824,4426.5) ; v1(4932,4145.5) 4934,4147.5 4961,4147.5 4977,4131.5 4995,4131.5 5016,4110.5 5171,4110.5 5177,4116.5 5203,4116.5 5217,4102.5 5231,4102.5 5243.96,4115.46 U10.N19@5251.11,4115.46
  Bottom Layer w4: v1(4824,4426.5) 4824,4279.5 4914,4189.5 4914,4163.5 v1(4932,4145.5)
LCD_DE: LCD1.13 U10.M18 | length 743.2
  Top Layer w4: LCD1.13@4585.7,3991.9 4653.4,3991.9 4655,3993.5 v1(4657,3993.5) ; v1(5264.07,4102.5) U10.M18@5276.7,4089.87
  Bottom Layer w4: v1(4657,3993.5) 4657,3995.5 4661,3999.5 4726,3999.5 4798,4071.5 5203,4071.5 5234,4102.5 v1(5264.07,4102.5)
LCD_HS: LCD1.15 U10.W18 | length 878.4
  Top Layer w4: LCD1.15@4585.7,4031.2 4690.7,4031.2 v1(4715,4055.5) ; v1(5239,4281.5) 5240,4280.5 5265.2,4280.5 U10.W18@5276.7,4269
  Mid-Layer 2 w4: v1(4715,4055.5) 4738,4078.5 4738,4183.5 4789,4234.5 5221,4234.5 5239,4252.5 v1(5239,4281.5)
LCD_PWM: R21.2 U5.4 U10.K15 | length 2481.5
  Top Layer w8: R21.2@4110,4900.5 4110,4859.66 U5.4@4121.76,4847.9
  Top Layer w10: v1(5341,4051.5) 5341,4051.16 U10.K15@5353.47,4038.68
  Top Layer w20: v6(4086,4847.5) 4121.36,4847.5 U5.4@4121.76,4847.9
  Mid-Layer 2 w4: v6(4086,4847.5) 4086,3979.5 4297,3768.5 4656,3768.5 4886,3998.5 5338,3998.5 5357,4017.5 5357,4035.5 v1(5341,4051.5)
LCD_RST: LCD1.6 U10.Y18 | length 1058.9
  Top Layer w4: LCD1.6@4585.7,3854.1 4617.6,3854.1 v1(4630,3866.5) ; v1(5026,4275.5) 5027,4275.5 5036,4266.5 5169,4266.5 5209,4306.5 5264.8,4306.5 U10.Y18@5276.7,4294.59
  Mid-Layer 1 w4: v1(4630,3866.5) 4630,4057.5 4694,4121.5 4694,4217.5 4752,4275.5 v1(5026,4275.5)
LCD_SCK: LCD1.10 U10.K17 | length 770.5
  Top Layer w5: LCD1.10@4585.7,3932.8 4701.3,3932.8 v1(4702,3933.5)
  Top Layer w8: v3(5291,4050.5) 5302.29,4039.21 U10.K17@5302.29,4038.68
  Bottom Layer w4: v1(4702,3933.5) 4711,3933.5 4820,4042.5 5283,4042.5 v3(5291,4050.5)
LCD_SDA: LCD1.9 U10.K16 | length 809.8
  Top Layer w5: LCD1.9@4585.7,3913.1 4716.6,3913.1 v1(4734,3930.5)
  Top Layer w8: v3(5316.06,4050.5) U10.K16@5327.88,4038.68
  Bottom Layer w4: v1(4734,3930.5) 4734,3940.5 4827,4033.5 5299.06,4033.5 v3(5316.06,4050.5)
LCD_VS: LCD1.14 U10.V18 | length 865.3
  Top Layer w4: LCD1.14@4585.7,4011.6 4701.1,4011.6 v1(4752,4062.5) ; v1(5264,4256.5) 5264,4256.12 v1@5264.61,4255.5 ; v1@5265,4255.5 v1@5264.61,4255.5 ; U10.V18@5276.7,4243.41 v1@5264.61,4255.5
  Mid-Layer 2 w4: v1(4752,4062.5) 4752,4176.5 4798,4222.5 5230,4222.5 v1(5264,4256.5)
LDOA_OUT: C34.2 C35.2 U10.J4 U10.J5 U10.K4 U10.K5 U10.L7 U10.M17 U10.P14 U10.R16 | length 926.5
  Top Layer w9: v1(5546,4077.5) 5558.2,4065.3 5558.2,4064.28 5583.78,4064.28 5622.18,4025.89 ; U10.J5@5609.38,4013.09 5622.18,4025.89 ; U10.J4@5634.97,4013.09 5622.18,4025.89 ; U10.K4@5634.97,4038.68 5622.18,4025.89
  Top Layer w10: C34.2@5104,4088.5 v1(5132,4088.5) ; C35.2@5104,4186.5 v1(5131,4186.5) ; v1@5302,4071.5 v1(5302.29,4071.79) U10.M17@5302.29,4089.87 ; U10.R16@5327.88,4166.64 5318,4156.76 5318,4146.5 5331,4133.5 5354,4133.5 5361.55,4141.05 U10.P14@5379.06,4141.05
  Mid-Layer 1 w9: v1(5357,4136.5) 5362,4131.5 5442,4131.5 5478,4095.5 5528,4095.5 v1(5546,4077.5)
  Mid-Layer 1 w10: v1(5132,4088.5) 5167,4053.5 5269,4053.5 5287.29,4071.79 v1(5302.29,4071.79) 5328.29,4071.79 5339,4082.5 5339,4118.5 v1(5357,4136.5)
  Mid-Layer 2 w10: v1(5131,4186.5) 5132,4185.5 v1(5132,4088.5)
LDOB_OUT: U10.N7
LEDA: C54.2 C74.2 D2.1 LCD1.1 U5.5 | length 1485.4
  Top Layer w12: D2.1@4118.8,4703.5 4118.8,4661.7 4164,4616.5 4164,4512.5 4469,4207.5 4469,3786.5 4499.9,3755.6 LCD1.1@4585.7,3755.6 4665.37,3755.6 C54.2@4665.47,3755.5
  Top Layer w18: C74.2@4071.53,4692.5 4071,4693.03 4071,4719.5 ; D2.1@4118.8,4703.5 4087,4703.5 4071,4719.5 ; U5.5@4121.76,4810.5 4087,4810.5 4071,4794.5 4071,4719.5
LEDK: LCD1.2 LCD1.3 R22.2 U5.3 | length 1470.7
  Top Layer w8: U5.3@4212.24,4847.9 4222,4857.66 R22.2@4222,4899.5
  Top Layer w12: U5.3@4212.24,4847.9 4184.4,4847.9 4164,4827.5 4164,4654.5 4190,4628.5 4190,4527.5 4492,4225.5 4492,3798.5 4495.5,3795 ; LCD1.2@4585.7,3775.3 4515.2,3775.3 4495.5,3795 ; LCD1.3@4585.7,3795 4495.5,3795
LPCLK: R30.1 U7.20 U10.C6 | length 591.6
  Top Layer w4: U7.20@5262.56,3651.07 v1(5312.56,3651.07) 5422.44,3651.07 R30.1@5445,3628.5 ; U10.C6@5583.79,3859.55 v1(5594.85,3848.5) v1@5595,3848.5
  Bottom Layer w4: v1(5312.56,3651.07) 5313.56,3651.07 5379,3716.5 5497,3716.5 5594.85,3814.35 v1(5594.85,3848.5)
PE4: H1.9 U10.T2 | length 1220.5
  Top Layer w4: U10.T2@5686.15,4192.23 5717.73,4192.23 5799.35,4273.85 5874.65,4273.85 v3(5885,4263.5)
  Mid-Layer 1 w4: v3(5885,4263.5) 5885,4232.5 6037,4080.5 6037,3560.5 6114,3483.5 6193,3483.5 v3(6214,3462.5)
PE5: H1.7 U10.T3 | length 1140
  Top Layer w4: U10.T3@5660.56,4192.23 5672.3,4180.5 5720,4180.5 5799,4259.5 v3(5856,4259.5)
  Mid-Layer 1 w4: v3(5856,4259.5) 5856,4248.5 6028,4076.5 6028,3555.5 6107,3476.5 v3(6107,3456.5)
PE6: H1.5 U10.R1 | length 1018.9
  Top Layer w4: U10.R1@5711.74,4166.64 5720.14,4166.64 5799,4245.5 5832,4245.5 v3(5833,4244.5)
  Mid-Layer 1 w4: v3(5833,4244.5) 5847,4244.5 6019,4072.5 6019,3476.5 v3(6011,3468.5)
PE7: H1.6 U10.R2 | length 813.1
  Top Layer w4: U10.R2@5686.15,4166.64 5697.3,4155.5 5723,4155.5 5788,4220.5 v3(5822,4220.5)
  Mid-Layer 1 w4: v3(5822,4220.5) 5859,4220.5 6010,4069.5 6010,3689.5 6000,3679.5 v3(5999,3679.5)
PE8: H1.11 U10.R3 | length 1465.6
  Top Layer w4: v3(5640,4143.5) 5640,4146.08 U10.R3@5660.56,4166.64
  Mid-Layer 1 w4: v3(5927,4252.5) 5944,4235.5 5944,4186.5 6046,4084.5 6046,3565.5 6118,3493.5 6280,3493.5 v3(6311,3462.5)
  Mid-Layer 2 w4: v3(5640,4143.5) 5647,4150.5 5675,4150.5 5832,4307.5 5893,4307.5 5927,4273.5 v3(5927,4252.5)
PE9: H1.3 U10.P2 | length 1010.5
  Top Layer w4: U10.P2@5686.15,4141.05 5691.6,4146.5 5730,4146.5 5785,4201.5 5813,4201.5 v3(5820,4194.5)
  Mid-Layer 1 w4: v3(5820,4194.5) 5873,4194.5 6001,4066.5 6001,3816.5 5932,3747.5 5932,3664.5 5910,3642.5 v3(5910,3489.5)
PE10: H1.4 U10.P3 | length 826.5
  Top Layer w4: U10.P3@5660.56,4141.05 5672.11,4129.5 5694,4129.5 5702,4137.5 5737,4137.5 5777,4177.5 v3(5798,4177.5)
  Mid-Layer 1 w4: v3(5798,4177.5) 5877,4177.5 5992,4062.5 5992,3820.5 5922,3750.5 5922,3681.5 v3(5913,3672.5)
PE11: H1.1 U10.N1 | length 983.1
  Top Layer w4: U10.N1@5711.74,4115.46 5723.78,4127.5 5742,4127.5 5765,4150.5 v3(5801,4150.5)
  Mid-Layer 1 w4: v3(5801,4150.5) 5890,4150.5 5983,4057.5 5983,3823.5 5843,3683.5 5843,3611.5 5812,3580.5 v3(5812,3469.5)
PE12: H1.12 U10.R5 | length 1565.2
  Top Layer w4: v3(5578,4148.5) 5579,4147.5 5593,4147.5 5609.38,4163.88 U10.R5@5609.38,4166.64
  Mid-Layer 1 w4: v3(5982,4253.5) 5963,4234.5 5963,4193.5 6064,4092.5 6064,3609.5 6088,3585.5 6292,3585.5 6314,3607.5 v3(6314,3661.5)
  Mid-Layer 2 w4: v3(5578,4148.5) 5579,4147.5 5594,4147.5 5615,4168.5 5668,4168.5 5824,4324.5 5911,4324.5 v3(5982,4253.5)
PE13: H1.13 U10.R4 | length 1594.3
  Top Layer w4: v3(5617,4146.5) 5617,4148.67 U10.R4@5634.97,4166.64
  Mid-Layer 1 w4: v3(5954,4252.5) 5954,4189.5 6055,4088.5 6055,3570.5 6123,3502.5 6377,3502.5 v3(6414,3465.5)
  Mid-Layer 2 w4: v3(5617,4146.5) 5630,4159.5 5671,4159.5 5828,4316.5 5901,4316.5 5954,4263.5 v3(5954,4252.5)
PE14: H1.2 U10.N4 | length 848.9
  Top Layer w4: U10.N4@5634.97,4115.46 5647.94,4102.5 5718,4102.5 5733,4117.5 5747,4117.5 5762,4132.5 v3(5843,4132.5)
  Mid-Layer 1 w4: v3(5815,3667.5) 5974,3826.5 5974,4053.5 5886,4141.5 5852,4141.5 v3(5843,4132.5)
PE15: H1.10 U10.N5 | length 1460.9
  Top Layer w4: v3(5597,4128.5) 5597,4127.85 U10.N5@5609.38,4115.46
  Mid-Layer 1 w4: v3(6014,4245.5) 5996,4245.5 5973,4222.5 5973,4198.5 6073,4098.5 6073,3614.5 6093,3594.5 6190,3594.5 6211,3615.5 v3(6211,3658.5)
  Mid-Layer 2 w4: v3(5597,4128.5) 5667,4128.5 5837,4298.5 5888,4298.5 5909,4277.5 5909,4242.5 5924,4227.5 5996,4227.5 v3(6014,4245.5)
PE16: H1.8 U10.N6 | length 1159.2
  Top Layer w4: v3@5572,4127.5 v3(5572,4127.26) U10.N6@5583.79,4115.46
  Mid-Layer 1 w4: v3(5995,4208.5) 5995,4190.5 6082,4103.5 6082,3697.5 v3(6110,3669.5)
  Mid-Layer 2 w4: v3(5572,4127.26) 5587.76,4111.5 5602,4111.5 5611,4120.5 5671,4120.5 5838,4287.5 5884,4287.5 5900,4271.5 5900,4236.5 5920,4216.5 5987,4216.5 v3(5995,4208.5)
PG11: R35.1 U7.18 U10.D4 | length 571.4
  Top Layer w4: U7.18@5262.56,3619.57 5324.06,3619.57 v1(5333,3628.5) R35.1@5368,3628.5 ; U10.D4@5634.97,3885.14 5646.61,3873.5 v1(5647,3873.5)
  Bottom Layer w4: v1(5333,3628.5) 5333,3658.5 5382,3707.5 5501,3707.5 5605,3811.5 5605,3832.5 5646,3873.5 v1(5647,3873.5)
RESET: R34.1 RESET.2 U10.M2 | length 671.7
  Top Layer w6: U10.M2@5686.15,4089.87 5697.52,4078.5 v1(5698,4078.5) ; v1(5977,4397.5) 6037,4397.5 6095,4455.5 RESET.2@6092.7,4457.8
  Top Layer w10: RESET.2@6092.7,4457.8 6104,4469.1 R34.1@6104,4508.5
  Mid-Layer 1 w6: v1(5698,4078.5) 5755,4135.5 5755,4209.5 5911,4365.5 5945,4365.5 v1(5977,4397.5)
SA0: U4.N3 U10.V11 | length 563.7
  Top Layer w4: U4.N3@5326.03,4742.62 5326.03,4715.11 5341.24,4699.89 v2(5358.24,4699.89) ; v2(5442.85,4256.19) U10.V11@5455.64,4243.39
  Bottom Layer w4: v2(5358.24,4699.89) 5356.38,4464.76 5420.24,4400.89 5420.24,4381.89 5442.85,4359.29 v2(5442.85,4256.19)
SA1: U4.P7 U10.W13 | length 656.1
  Top Layer w4: v2(5243.39,4461.89) 5216.24,4461.89 5171.24,4506.89 5171.24,4597.89 5222.24,4648.89 5247.24,4648.89 5258.24,4637.89 5273.27,4637.89 5294.27,4616.89 U4.P7@5294.27,4617.38 ; v2(5258.24,4405.89) 5291.24,4405.89 5355.24,4341.89 5398.24,4341.89 5419.24,4320.89 5419.24,4283.76 U10.W13@5404.46,4268.98
  Bottom Layer w4: v2(5243.39,4461.89) 5243.39,4420.75 v2(5258.24,4405.89)
SA2: U4.P3 U10.V13 | length 648.2
  Top Layer w4: v2(5279.39,4715.89) 5294.27,4730.78 U4.P3@5294.27,4742.87 ; v2(5373.1,4208.89) 5373.1,4212.03 U10.V13@5404.46,4243.39
  Bottom Layer w4: v2(5279.39,4715.89) 5279.39,4602.04 5262.24,4584.89 5262.24,4527.89 5283.24,4506.89 5283.24,4439.89 5323.24,4399.89 5323.24,4375.89 5382.24,4316.89 5382.24,4218.04 v2(5373.1,4208.89)
SA3: U4.N2 U10.V14 | length 846.9
  Top Layer w4: U4.N2@5325.77,4774.37 5309.13,4757.73 5309.13,4712.78 5296.24,4699.89 5225.76,4699.89 5219.76,4705.89 5199.24,4705.89 5123.24,4629.89 5123.24,4478.89 5228.24,4373.89 5293.24,4373.89 5348.24,4318.89 5370.24,4318.89 5390.78,4298.36 5390.78,4255.3 U10.V14@5378.87,4243.39
SA4: U4.P8 U10.T15 | length 611.5
  Top Layer w4: v2@5246.24,4601.89 5277.77,4601.89 U4.P8@5294.27,4585.39 ; v2(5340.49,4179.42) U10.T15@5353.28,4192.21
  Bottom Layer w4: v2(5247.04,4601.15) 5193.24,4547.35 5193.24,4386.89 5225.24,4354.89 5271.24,4354.89 5331.24,4294.89 5331.24,4266.9 5323.24,4258.9 5323.24,4196.66 v2(5340.49,4179.42)
SA5: U4.P2 U10.R15 | length 834.4
  Top Layer w4: v2(5278.53,4790.12) U4.P2@5294.27,4774.37 ; v2(5340.49,4153.83) U10.R15@5353.28,4166.62
  Bottom Layer w4: v2(5278.53,4790.12) 5170.24,4681.84 5170.24,4372.89 5217.24,4325.89 5246.24,4325.89 5310.37,4261.76 5310.37,4201.03 5297.37,4188.03 5297.37,4172.03 5315.58,4153.83 v2(5340.49,4153.83)
SA6: U4.R8 U10.U13 | length 546.9
  Top Layer w4: v2(5237.24,4518.89) 5256.24,4518.89 5261.24,4523.89 5261.24,4532.89 5247.24,4546.89 5247.24,4569.85 U4.R8@5262.78,4585.39 ; v2(5366.08,4179.42) U10.U13@5404.46,4217.8
  Bottom Layer w4: v2(5237.24,4518.89) 5237.24,4499.89 5258.24,4478.89 5258.24,4428.89 5293.24,4393.89 5293.24,4370.89 5350.24,4313.89 5350.24,4219.67 5357.24,4212.67 5357.24,4188.25 v2(5366.08,4179.42)
SA7: U4.R2 U10.W15 | length 782.4
  Top Layer w4: U4.R2@5262.78,4774.37 5277.24,4759.91 5277.24,4735.89 5265.24,4723.89 5198.24,4723.89 5111.24,4636.89 5111.24,4471.89 5223.24,4359.89 5292.24,4359.89 5344.24,4307.89 5361.24,4307.89 5368.24,4300.89 5368.24,4283.94 U10.W15@5353.28,4268.98
SA8: U4.T8 U10.U15 | length 662.9
  Top Layer w4: v2@5202.76,4511.89 v2(5209.24,4511.89) 5195.5,4519.15 5195.5,4544.15 5209.5,4558.15 5209.5,4569.15 5201.5,4577.15 5196.5,4577.15 5193.5,4580.15 5193.5,4585.15 5198.5,4590.15 5205.5,4590.15 5218.03,4577.62 5223.51,4577.62 U4.T8@5230.51,4584.62 ; v2(5340.49,4205.01) U10.U15@5353.28,4217.8
  Bottom Layer w4: v2(5209.24,4511.89) 5209.24,4471.25 ccw(c5214.24,4471.25) 5214.24,4466.25 5213.24,4466.25 cw(c5213.24,4461.25) 5218.24,4461.25 cw(c5213.24,4461.25) 5213.24,4456.25 5206.24,4456.25 ccw(c5206.24,4451.25) 5201.24,4451.25 ccw(c5206.24,4451.25) 5206.24,4446.25 5213.24,4446.25 cw(c5213.24,4441.25) 5218.24,4441.25 cw(c5213.24,4441.25) 5213.24,4436.25 5206.24,4436.25 ccw(c5206.24,4431.25) 5201.24,4431.25 ccw(c5206.24,4431.25) 5206.24,4426.25 5213.24,4426.25 cw(c5213.24,4421.25) 5218.24,4421.25 cw(c5213.24,4421.25) 5213.24,4416.25 5206.24,4416.25 ccw(c5206.24,4411.25) 5201.24,4411.25 ccw(c5206.24,4411.25) 5206.24,4406.25 5204.24,4406.25 cw(c5204.24,4401.25) 5209.24,4401.25 5209.24,4392.89 5231.48,4370.66 5253.43,4370.66 ccw(c5253.43,4375.66) 5258.43,4375.66 5258.43,4384.89 cw(c5263.43,4384.89) 5263.43,4389.89 cw(c5263.43,4384.89) 5268.43,4384.89 5268.43,4375.66 ccw(c5273.43,4375.66) 5273.43,4370.66 5274.48,4370.66 5340.49,4304.65 v2(5340.49,4205.01)
  other v2: 5209.24,4511.89 5209.24,4511.89
SA9: U4.R3 U10.V16 | length 783.6
  Top Layer w4: U4.R3@5262.78,4742.87 5248.91,4756.75 5196.1,4756.75 5087.24,4647.89 5087.24,4458.89 5214.24,4331.89 5287.24,4331.89 5340.24,4278.89 5340.24,4255.94 U10.V16@5327.69,4243.39
SA10: U4.L7 U10.R9 | length 611.1
  Top Layer w4: U4.L7@5388.76,4616.89 v2(5388.76,4658.89) ; v2(5494.04,4179.42) U10.R9@5506.83,4166.62
  Bottom Layer w4: v2(5388.76,4658.89) 5388.76,4645.41 5381.24,4637.89 5381.24,4489.89 5462.24,4408.89 5462.24,4227.89 5453.24,4218.89 5453.24,4195.89 5469.72,4179.42 v2(5494.04,4179.42)
SA11: U4.R7 U10.Y13 | length 550.2
  Top Layer w4: v2(5226.24,4485.89) 5211.24,4485.89 5184.24,4512.89 5184.24,4592.89 5223.99,4632.64 5247.04,4632.64 U4.R7@5262.78,4616.89 ; v2(5241.24,4389.89) 5292.24,4389.89 5352.24,4329.89 5387.24,4329.89 5404.46,4312.67 U10.Y13@5404.46,4294.57
  Bottom Layer w4: v2(5226.24,4485.89) 5226.24,4404.89 v2(5241.24,4389.89)
SA12: U4.N7 U10.W12 | length 815.9
  Top Layer w4: v2(5199.24,4683.89) 5135.24,4619.89 5135.24,4485.89 5200.24,4420.89 5291.24,4420.89 5358.24,4353.89 5411.24,4353.89 5430.05,4335.08 U10.W12@5430.05,4268.98 ; v2(5262.24,4657.89) 5308.24,4657.89 5325.77,4640.36 U4.N7@5325.77,4616.89
  Bottom Layer w4: v2(5199.24,4683.89) 5236.24,4683.89 v2(5262.24,4657.89)
SA13: U4.T3 U10.Y15 | length 675.5
  Top Layer w4: U4.T3@5231.28,4742.87 5199.22,4742.87 5099.24,4642.89 5099.24,4465.89 5219.24,4345.89 5289.24,4345.89 5340.56,4294.57 U10.Y15@5353.28,4294.57
SA14: U4.T7 U10.W16 | length 585.9
  Top Layer w4: v2(5215.54,4601.15) U4.T7@5231.28,4616.89 ; v2(5314.9,4281.78) U10.W16@5327.69,4268.98
  Bottom Layer w4: v2(5215.54,4601.15) 5237.24,4622.85 5237.24,4643.89 5227.24,4653.89 5205.24,4653.89 5181.24,4629.89 5181.24,4380.89 5222.24,4339.89 5256.78,4339.89 v2(5314.9,4281.78)
SA15: U4.M7 U10.Y11 | length 786
  Top Layer w4: U4.M7@5357.26,4616.89 5357.26,4641.87 5324.24,4674.89 5232.24,4674.89 5159.24,4601.89 5159.24,4498.89 5212.24,4445.89 5298.24,4445.89 5366.24,4377.89 5432.24,4377.89 5455.64,4354.49 U10.Y11@5455.64,4294.57
SBA0: U4.M2 U10.W11 | length 937.4
  Top Layer w4: U4.M2@5357.26,4774.37 5343.39,4760.5 5343.39,4728.75 5351.24,4720.89 5363.24,4720.89 5377.24,4706.89 5377.24,4691.89 5361.24,4675.89 5345.24,4675.89 5333.24,4687.89 5227.24,4687.89 5147.24,4607.89 5147.24,4491.89 5205.24,4433.89 5294.24,4433.89 5362.24,4365.89 5421.24,4365.89 5442.24,4344.89 5442.24,4282.38 U10.W11@5455.64,4268.98
SBA1: U4.N8 U10.W14 | length 647.9
  Top Layer w4: v2(5261.24,4502.89) 5261.24,4471.41 5274.5,4458.15 5300.5,4458.15 5311.9,4469.55 5311.9,4475.57 cw(c5316.9,4475.57) 5316.9,4480.57 5325.3,4480.57 ccw(c5325.3,4485.57) 5330.3,4485.57 ccw(c5325.3,4485.57) 5325.3,4490.57 5298.5,4490.57 cw(c5298.5,4495.57) 5293.5,4495.57 cw(c5298.5,4495.57) 5298.5,4500.57 5325.3,4500.57 ccw(c5325.3,4505.57) 5330.3,4505.57 ccw(c5325.3,4505.57) 5325.3,4510.57 5298.5,4510.57 cw(c5298.5,4515.57) 5293.5,4515.57 cw(c5298.5,4515.57) 5298.5,4520.57 5306.9,4520.57 ccw(c5306.9,4525.57) 5311.9,4525.57 5311.9,4571.52 U4.N8@5325.77,4585.39 ; v2(5366.08,4256.19) U10.W14@5378.87,4268.98
  Bottom Layer w4: v2(5261.24,4502.89) 5270.24,4493.89 5270.24,4434.89 5309.24,4395.89 5309.24,4371.89 5366.08,4315.06 v2(5366.08,4256.19)
SBA2: U4.M3 U10.V10 | length 572.3
  Top Layer w4: U4.M3@5357.26,4742.87 5371.24,4728.89 5378.24,4728.89 v2(5389.24,4717.89) ; v2(5446.24,4396.89) 5469.34,4373.8 5469.34,4255.3 U10.V10@5481.24,4243.39
  Bottom Layer w4: v2(5389.24,4717.89) 5376.24,4704.89 5376.24,4691.89 5368.24,4683.89 5368.24,4474.89 v2(5446.24,4396.89)
SCAS: U4.K3 U10.T9 | length 699.4
  Top Layer w4: U4.K3@5420.26,4742.87 v2(5436.01,4758.62) ; U10.T9@5506.83,4192.21 v2(5519.63,4179.42)
  Bottom Layer w4: v2(5436.01,4758.62) 5453.24,4741.39 5453.24,4597.36 5442.17,4586.28 5431.63,4586.28 5421.15,4575.8 5421.15,4563.49 5421.24,4563.4 5421.24,4510.89 5496.24,4435.89 5496.24,4333.89 5517.24,4312.89 5517.24,4285.89 5502.24,4270.89 5502.24,4220.89 5519.63,4203.51 v2(5519.63,4179.42)
SCKE0: U4.K9 U10.W9 | length 771.4
  Top Layer w4: U4.K9@5420.26,4553.9 5436.24,4537.92 5436.24,4491.89 5484.24,4443.89 5588.24,4443.89 5607.24,4462.89 5667.24,4462.89 5674.24,4455.89 5674.24,4437.89 5644.24,4407.89 5592.24,4407.89 5577.24,4422.89 5532.24,4422.89 5526.97,4417.63 cw(c5523.44,4421.16) 5519.9,4417.63 5509.97,4427.56 ccw(c5506.44,4424.02) 5502.9,4427.55 ccw(c5506.44,4424.02) 5502.9,4420.48 5512.83,4410.56 cw(c5509.3,4407.02) 5512.83,4403.48 cw(c5509.3,4407.02) 5505.76,4403.48 5495.83,4413.41 ccw(c5492.3,4409.88) 5488.76,4413.41 ccw(c5492.3,4409.88) 5488.76,4406.34 5498.69,4396.41 cw(c5495.15,4392.88) 5498.69,4389.34 5492.24,4382.9 5492.24,4283.57 U10.W9@5506.83,4268.98
SCKE1: U4.J9 U10.Y9 | length 781.8
  Top Layer w4: U4.J9@5451.75,4553.9 5451.75,4514.38 5451.5,4514.13 5451.5,4494.15 5476.5,4469.15 5483.11,4469.15 cw(c5483.11,4464.15) 5488.11,4464.15 ccw(c5493.11,4464.15) 5493.11,4459.15 ccw(c5493.11,4464.15) 5498.11,4464.15 5498.11,4474.15 cw(c5503.11,4474.15) 5503.11,4479.15 cw(c5503.11,4474.15) 5508.11,4474.15 5508.11,4464.15 ccw(c5513.11,4464.15) 5513.11,4459.15 ccw(c5513.11,4464.15) 5518.11,4464.15 5518.11,4474.15 cw(c5523.11,4474.15) 5523.11,4479.15 cw(c5523.11,4474.15) 5528.11,4474.15 5528.11,4464.15 ccw(c5533.11,4464.15) 5533.11,4459.15 ccw(c5533.11,4464.15) 5538.11,4464.15 5538.11,4474.15 cw(c5543.11,4474.15) 5543.11,4479.15 cw(c5543.11,4474.15) 5548.11,4474.15 5548.11,4464.15 ccw(c5553.11,4464.15) 5553.11,4459.15 ccw(c5553.11,4464.15) 5558.11,4464.15 5558.11,4474.15 cw(c5563.11,4474.15) 5563.11,4479.15 cw(c5563.11,4474.15) 5568.11,4474.15 5568.11,4464.15 ccw(c5573.11,4464.15) 5573.11,4459.15 ccw(c5573.11,4464.15) 5578.11,4464.15 cw(c5583.11,4464.15) 5583.11,4469.15 5595.5,4469.15 5602.24,4475.89 5676.24,4475.89 5690.24,4461.89 5690.24,4426.89 5658.24,4394.89 5585.24,4394.89 5570.24,4409.89 5551.24,4409.89 5518.24,4376.89 5518.24,4305.98 U10.Y9@5506.83,4294.57
SCKN: R11.2 U4.K7 U10.U10 | length 997.5
  Top Layer w4: v2(5407.7,4631.46) 5408.7,4630.46 5408.7,4628.45 U4.K7@5420.26,4616.89 ; v2(5468.45,4205.01) U10.U10@5481.24,4217.8
  Mid-Layer 1 w4: v2(5407.7,4631.46) 5416.7,4640.46 5416.7,4675.46 5449.75,4708.5 5696.75,4708.5 5713.7,4725.46 5713.7,4796.46 5724.7,4807.46 5732.7,4807.46 5742.7,4817.46 v1(5747.7,4817.46)
  Bottom Layer w4: v2@5408.7,4636.83 5408.7,4628.45 5416.26,4620.9 5416.26,4615.91 5396.24,4595.89 5396.24,4503.58 5477.24,4422.58 5477.24,4213.91 v2(5468.45,4205.01) v2@5468.45,4205.12
SCKP: R11.1 U4.J7 U10.T10 | length 982
  Top Layer w4: v2(5436.01,4632.64) U4.J7@5451.75,4616.89 ; U10.T10@5481.24,4192.21 v2(5494.04,4205.01)
  Mid-Layer 1 w4: v2(5436.01,4632.64) 5424.7,4643.94 5424.7,4671.46 5452.75,4699.5 5700.75,4699.5 5721.7,4720.46 5721.7,4791.46 5728.7,4798.46 5733.7,4798.46 5740.7,4791.46 v1(5747.7,4791.46)
  Bottom Layer w4: v2(5436.01,4632.64) 5424.26,4620.9 5424.26,4612.6 5404.24,4592.58 5404.24,4506.89 5485.24,4425.89 5485.24,4213.91 v2(5494.04,4205.01) v2@5494.04,4205.12
SCS0: U4.L2 U10.R12 | length 726.9
  Top Layer w4: v2(5373.02,4758.63) U4.L2@5388.76,4774.37 ; U10.R12@5430.05,4166.62 v2(5442.85,4153.83)
  Bottom Layer w4: v2(5373.02,4758.63) 5348.98,4758.63 5326.24,4735.89 5326.24,4470.89 5378.24,4418.89 5378.24,4394.89 5427.24,4345.89 5427.24,4238.89 5442.85,4223.29 v2(5442.85,4153.83)
SCS1: U4.L1 U10.R13 | length 789
  Top Layer w4: v2(5373.02,4790.12) U4.L1@5388.76,4805.86 ; v2(5391.67,4153.83) U10.R13@5404.46,4166.62
  Bottom Layer w4: v2(5373.02,4790.12) 5357.47,4790.12 5316.24,4748.89 5316.24,4461.89 5363.24,4414.89 5363.24,4390.89 5416.24,4337.89 5416.24,4231.89 5433.24,4214.89 5433.24,4171.4 5415.67,4153.83 v2(5391.67,4153.83)
SDC0_CLK: R47.2 SIM1.5 | length 1519.9
  Top Layer w4: R47.2@5802,3876.5 5837,3876.5 5901,3812.5 6574,3812.5 6645,3883.5 6645,4058.5 6703.3,4116.8 6767.3,4116.8 6832,4181.5 6839,4181.5 6844,4176.5 6844,4170.5 6822,4148.5 6822,4144.5 6826,4140.5 6831,4140.5 6856,4165.5 6860,4165.5 6864,4161.5 6864,4156.5 6852,4144.5 6852,4136.5 6871.7,4116.8 SIM1.5@6911.1,4116.8
SDC0_CMD: SIM1.3 U10.D1 | length 1501.1
  Top Layer w4: U10.D1@5711.74,3885.14 5741.64,3885.14 5759,3902.5 5826,3902.5 5906,3822.5 6569,3822.5 6634,3887.5 6634,4064.5 6697,4127.5 6762,4127.5 6828,4193.5 6901.2,4193.5 SIM1.3@6911.1,4203.4
SDC0_D0: SIM1.7 U10.C1 | length 1622.9
  Top Layer w4: U10.C1@5711.74,3859.55 5716.8,3854.5 5845,3854.5 5897,3802.5 6580,3802.5 6655,3877.5 6655,4054.5 6706,4105.5 6777,4105.5 6786,4096.5 6794,4096.5 6816,4118.5 6824,4118.5 6828,4114.5 6828,4109.5 6806,4087.5 6806,4076.5 6810,4072.5 6821,4072.5 6842,4093.5 6847,4093.5 6852,4088.5 6852,4082.5 6832,4062.5 6832,4050.5 6852.3,4030.2 SIM1.7@6911.1,4030.2
SDC0_D1: SIM1.8 U10.C2 | length 1526.7
  Top Layer w4: U10.C2@5686.15,3859.55 5700.2,3845.5 5839,3845.5 5892,3792.5 6585,3792.5 6666,3873.5 6666,4051.5 6709,4094.5 6772,4094.5 6879,3987.5 6910.5,3987.5 SIM1.8@6911.1,3986.9
SDC0_D2: SIM1.1 U10.E2 | length 1558.4
  Top Layer w4: U10.E2@5686.15,3910.73 5690.39,3906.5 5735,3906.5 5751,3922.5 5836,3922.5 5916,3842.5 6558,3842.5 6612,3896.5 6612,4078.5 6684,4150.5 6755,4150.5 6894.5,4290 SIM1.1@6911.1,4290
